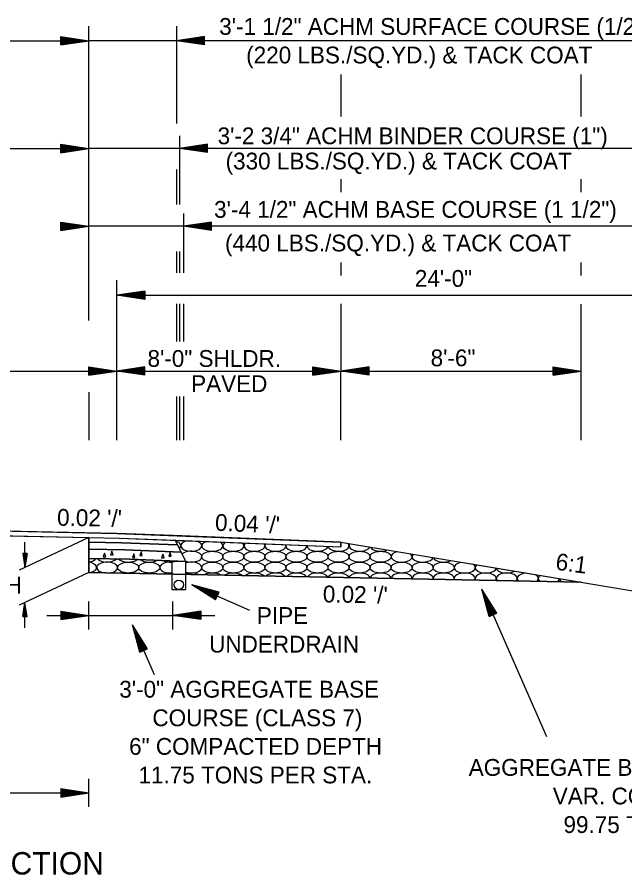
# Model space of a CAD drawing. Extents: x 1371763 to 1372860, y 385599 to 385872.
# Drawn here: x 1372369.02 to 1372390.7, y 385656.56 to 385687.17 of the extents above; entities that cross this region are included whole.
import ezdxf

# ---------------------------------------------------------------- set-up
doc = ezdxf.new("R2010")
doc.units = 0
doc.layers.add('R_Draft', color=7, linetype='Continuous')

msp = doc.modelspace()

# ---------------------------------------------------------------- linework, layer by layer
at = {"layer": 'R_Draft'}
for p, q in [((1372371.578, 385676.343), (1372371.579, 385686.852)), ((1372374.706, 385686.852), (1372374.706, 385683.373)), ((1372370.579, 385686.48), (1372371.579, 385686.33)), ((1372370.579, 385686.18), (1372370.579, 385686.48)), ((1372375.706, 385686.48), (1372374.706, 385686.33)), ((1372375.706, 385686.18), (1372375.706, 385686.48)), ((1372349.579, 385686.33), (1372371.579, 385686.33)), ((1372370.579, 385686.455), (1372371.412, 385686.33)), ((1372370.579, 385686.43), (1372371.24, 385686.33)), ((1372370.579, 385686.405), (1372371.074, 385686.33)), ((1372370.579, 385686.379), (1372370.904, 385686.33)), ((1372370.579, 385686.354), (1372370.737, 385686.33)), ((1372370.579, 385686.18), (1372371.579, 385686.33)), ((1372370.579, 385686.282), (1372370.904, 385686.33)), ((1372370.579, 385686.231), (1372371.24, 385686.33)), ((1372370.579, 385686.205), (1372371.412, 385686.33)), ((1372370.579, 385686.256), (1372371.074, 385686.33)), ((1372370.579, 385686.307), (1372370.737, 385686.33)), ((1372397.255, 385686.33), (1372371.579, 385686.33)), ((1372375.706, 385686.18), (1372374.706, 385686.33)), ((1372375.706, 385686.455), (1372374.873, 385686.33)), ((1372375.706, 385686.205), (1372374.873, 385686.33)), ((1372375.706, 385686.429), (1372375.045, 385686.33)), ((1372375.706, 385686.23), (1372375.045, 385686.33)), ((1372375.706, 385686.404), (1372375.211, 385686.33)), ((1372375.706, 385686.255), (1372375.211, 385686.33)), ((1372375.706, 385686.379), (1372375.381, 385686.33)), ((1372375.706, 385686.281), (1372375.381, 385686.33)), ((1372375.706, 385686.353), (1372375.548, 385686.33)), ((1372375.706, 385686.306), (1372375.548, 385686.33)), ((1372380.578, 385683.622), (1372380.578, 385685.122)), ((1372389.145, 385683.622), (1372389.145, 385685.122)), ((1372374.811, 385682.936), (1372374.811, 385680.483)), ((1372370.579, 385682.635), (1372371.579, 385682.485)), ((1372370.579, 385682.335), (1372370.579, 385682.635)), ((1372370.579, 385682.61), (1372371.412, 385682.485)), ((1372370.579, 385682.585), (1372371.24, 385682.485)), ((1372370.579, 385682.56), (1372371.074, 385682.485)), ((1372370.579, 385682.534), (1372370.904, 385682.485)), ((1372370.579, 385682.509), (1372370.737, 385682.485)), ((1372375.811, 385682.636), (1372374.811, 385682.486)), ((1372375.811, 385682.611), (1372374.978, 385682.486)), ((1372375.811, 385682.585), (1372375.15, 385682.486)), ((1372375.811, 385682.56), (1372375.316, 385682.486)), ((1372375.811, 385682.535), (1372375.486, 385682.486)), ((1372375.811, 385682.509), (1372375.653, 385682.486)), ((1372375.811, 385682.336), (1372375.811, 385682.636)), ((1372349.579, 385682.485), (1372371.579, 385682.485)), ((1372370.579, 385682.335), (1372371.579, 385682.485)), ((1372370.579, 385682.437), (1372370.904, 385682.485)), ((1372370.579, 385682.386), (1372371.24, 385682.485)), ((1372370.579, 385682.36), (1372371.412, 385682.485)), ((1372370.579, 385682.411), (1372371.074, 385682.485)), ((1372370.579, 385682.462), (1372370.737, 385682.485)), ((1372396.621, 385682.486), (1372371.579, 385682.486)), ((1372375.811, 385682.336), (1372374.811, 385682.486)), ((1372375.811, 385682.361), (1372374.978, 385682.486)), ((1372375.811, 385682.386), (1372375.15, 385682.486)), ((1372375.811, 385682.411), (1372375.316, 385682.486)), ((1372375.811, 385682.437), (1372375.486, 385682.486)), ((1372375.811, 385682.462), (1372375.653, 385682.486)), ((1372374.706, 385681.735), (1372374.706, 385680.483)), ((1372380.578, 385680.924), (1372380.578, 385681.39)), ((1372389.145, 385680.924), (1372389.145, 385681.39)), ((1372374.958, 385680.16), (1372374.958, 385678.045)), ((1372370.578, 385679.86), (1372371.578, 385679.71)), ((1372370.578, 385679.56), (1372370.578, 385679.86)), ((1372370.578, 385679.835), (1372371.411, 385679.71)), ((1372370.578, 385679.81), (1372371.239, 385679.71)), ((1372370.578, 385679.785), (1372371.073, 385679.71)), ((1372370.578, 385679.759), (1372370.903, 385679.71)), ((1372375.958, 385679.86), (1372374.958, 385679.71)), ((1372375.958, 385679.835), (1372375.125, 385679.71)), ((1372375.958, 385679.81), (1372375.297, 385679.71)), ((1372375.958, 385679.785), (1372375.464, 385679.71)), ((1372375.958, 385679.759), (1372375.633, 385679.71)), ((1372375.958, 385679.56), (1372375.958, 385679.86)), ((1372370.578, 385679.734), (1372370.736, 385679.71)), ((1372370.578, 385679.56), (1372371.578, 385679.71)), ((1372370.578, 385679.662), (1372370.903, 385679.71)), ((1372370.578, 385679.611), (1372371.239, 385679.71)), ((1372370.578, 385679.585), (1372371.411, 385679.71)), ((1372370.578, 385679.636), (1372371.073, 385679.71)), ((1372370.578, 385679.687), (1372370.736, 385679.71)), ((1372396.621, 385679.71), (1372371.579, 385679.71)), ((1372375.958, 385679.56), (1372374.958, 385679.71)), ((1372375.958, 385679.585), (1372375.125, 385679.71)), ((1372375.958, 385679.611), (1372375.297, 385679.71)), ((1372375.958, 385679.636), (1372375.464, 385679.71)), ((1372375.958, 385679.662), (1372375.633, 385679.71)), ((1372375.958, 385679.734), (1372375.8, 385679.71)), ((1372375.958, 385679.687), (1372375.8, 385679.71)), ((1372374.706, 385678.81), (1372374.706, 385678.045)), ((1372374.811, 385678.81), (1372374.811, 385678.045)), ((1372380.578, 385677.951), (1372380.578, 385678.416)), ((1372389.145, 385677.951), (1372389.145, 385678.416)), ((1372372.577, 385672.074), (1372372.578, 385677.788)), ((1372373.578, 385677.397), (1372372.578, 385677.247)), ((1372373.578, 385677.372), (1372372.745, 385677.247)), ((1372373.578, 385677.347), (1372372.917, 385677.247)), ((1372373.578, 385677.322), (1372373.084, 385677.247)), ((1372373.578, 385677.296), (1372373.253, 385677.247)), ((1372373.578, 385677.397), (1372373.578, 385677.097)), ((1372372.578, 385677.247), (1372396.577, 385677.247)), ((1372373.578, 385677.097), (1372372.578, 385677.247)), ((1372373.578, 385677.122), (1372372.745, 385677.247)), ((1372373.578, 385677.148), (1372372.917, 385677.247)), ((1372373.578, 385677.173), (1372373.084, 385677.247)), ((1372373.578, 385677.198), (1372373.253, 385677.247)), ((1372373.578, 385677.271), (1372373.42, 385677.247)), ((1372373.578, 385677.224), (1372373.42, 385677.247)), ((1372374.706, 385676.937), (1372374.706, 385675.595)), ((1372374.811, 385676.937), (1372374.811, 385675.595)), ((1372374.958, 385676.937), (1372374.958, 385675.595)), ((1372380.577, 385672.074), (1372380.578, 385676.935)), ((1372389.15, 385672.069), (1372389.15, 385676.934)), ((1372360.578, 385674.541), (1372372.578, 385674.541)), ((1372371.578, 385674.691), (1372372.578, 385674.541)), ((1372371.578, 385674.391), (1372371.578, 385674.691)), ((1372371.578, 385674.666), (1372372.411, 385674.541)), ((1372371.578, 385674.64), (1372372.239, 385674.541)), ((1372371.578, 385674.615), (1372372.072, 385674.541)), ((1372371.578, 385674.59), (1372371.903, 385674.541)), ((1372371.578, 385674.564), (1372371.736, 385674.541)), ((1372371.578, 385674.391), (1372372.578, 385674.541)), ((1372371.578, 385674.492), (1372371.903, 385674.541)), ((1372371.578, 385674.441), (1372372.239, 385674.541)), ((1372371.578, 385674.416), (1372372.411, 385674.541)), ((1372371.578, 385674.466), (1372372.072, 385674.541)), ((1372371.578, 385674.517), (1372371.736, 385674.541)), ((1372373.578, 385674.691), (1372372.578, 385674.541)), ((1372373.578, 385674.391), (1372372.578, 385674.541)), ((1372372.578, 385674.541), (1372380.578, 385674.541)), ((1372373.578, 385674.666), (1372372.745, 385674.541)), ((1372373.578, 385674.416), (1372372.745, 385674.541)), ((1372373.578, 385674.64), (1372372.917, 385674.541)), ((1372373.578, 385674.441), (1372372.917, 385674.541)), ((1372373.578, 385674.615), (1372373.083, 385674.541)), ((1372373.578, 385674.466), (1372373.083, 385674.541)), ((1372373.578, 385674.59), (1372373.253, 385674.541)), ((1372373.578, 385674.492), (1372373.253, 385674.541)), ((1372373.578, 385674.564), (1372373.42, 385674.541)), ((1372373.578, 385674.517), (1372373.42, 385674.541)), ((1372373.578, 385674.391), (1372373.578, 385674.691)), ((1372379.578, 385674.691), (1372380.578, 385674.541)), ((1372379.578, 385674.391), (1372379.578, 385674.691)), ((1372379.578, 385674.666), (1372380.411, 385674.541)), ((1372379.578, 385674.64), (1372380.239, 385674.541)), ((1372379.578, 385674.615), (1372380.072, 385674.541)), ((1372379.578, 385674.59), (1372379.903, 385674.541)), ((1372379.578, 385674.564), (1372379.736, 385674.541)), ((1372379.578, 385674.391), (1372380.578, 385674.541)), ((1372379.578, 385674.492), (1372379.903, 385674.541)), ((1372379.578, 385674.441), (1372380.239, 385674.541)), ((1372379.578, 385674.416), (1372380.411, 385674.541)), ((1372379.578, 385674.466), (1372380.072, 385674.541)), ((1372379.578, 385674.517), (1372379.736, 385674.541)), ((1372381.578, 385674.691), (1372380.578, 385674.541)), ((1372381.578, 385674.391), (1372380.578, 385674.541)), ((1372380.578, 385674.541), (1372389.149, 385674.54)), ((1372381.578, 385674.666), (1372380.745, 385674.541)), ((1372381.578, 385674.416), (1372380.745, 385674.541)), ((1372381.578, 385674.64), (1372380.917, 385674.541)), ((1372381.578, 385674.441), (1372380.917, 385674.541)), ((1372381.578, 385674.615), (1372381.083, 385674.541)), ((1372381.578, 385674.466), (1372381.083, 385674.541)), ((1372381.578, 385674.59), (1372381.253, 385674.541)), ((1372381.578, 385674.492), (1372381.253, 385674.541)), ((1372381.578, 385674.564), (1372381.42, 385674.541)), ((1372381.578, 385674.517), (1372381.42, 385674.541)), ((1372381.578, 385674.391), (1372381.578, 385674.691)), ((1372388.15, 385674.69), (1372389.15, 385674.54)), ((1372388.15, 385674.39), (1372388.15, 385674.69)), ((1372388.15, 385674.665), (1372388.983, 385674.54)), ((1372388.15, 385674.639), (1372388.811, 385674.54)), ((1372388.15, 385674.614), (1372388.644, 385674.54)), ((1372388.15, 385674.589), (1372388.475, 385674.54)), ((1372388.15, 385674.563), (1372388.308, 385674.54)), ((1372388.15, 385674.39), (1372389.15, 385674.54)), ((1372388.15, 385674.491), (1372388.475, 385674.54)), ((1372388.15, 385674.44), (1372388.811, 385674.54)), ((1372388.15, 385674.415), (1372388.983, 385674.54)), ((1372388.15, 385674.465), (1372388.644, 385674.54)), ((1372388.15, 385674.516), (1372388.308, 385674.54)), ((1372371.578, 385673.791), (1372371.578, 385672.074)), ((1372374.706, 385673.632), (1372374.706, 385672.074)), ((1372374.811, 385673.632), (1372374.811, 385672.074)), ((1372374.958, 385673.632), (1372374.958, 385672.074)), ((1372360.579, 385668.989), (1372372.577, 385668.749)), ((1372360.579, 385668.823), (1372372.661, 385668.581)), ((1372372.577, 385668.749), (1372380.577, 385668.43)), ((1372371.578, 385668.603), (1372369.091, 385667.431)), ((1372369.303, 385667.531), (1372369.303, 385668.431)), ((1372371.578, 385668.603), (1372371.578, 385668.436)), ((1372371.578, 385668.436), (1372371.578, 385668.186)), ((1372372.661, 385668.581), (1372380.577, 385668.265)), ((1372374.664, 385668.501), (1372374.748, 385668.333)), ((1372380.577, 385668.43), (1372396.577, 385665.763)), ((1372380.577, 385668.43), (1372380.577, 385668.265)), ((1372371.578, 385668.186), (1372371.578, 385667.853)), ((1372374.748, 385668.333), (1372374.854, 385668.121)), ((1372374.854, 385668.121), (1372375.022, 385667.784)), ((1372369.228, 385668.031), (1372369.303, 385667.531)), ((1372369.378, 385668.031), (1372369.228, 385668.031)), ((1372369.241, 385668.031), (1372369.303, 385667.615)), ((1372369.254, 385668.031), (1372369.303, 385667.701)), ((1372369.266, 385668.031), (1372369.303, 385667.784)), ((1372369.279, 385668.031), (1372369.303, 385667.869)), ((1372369.292, 385668.031), (1372369.303, 385667.952)), ((1372369.378, 385668.031), (1372369.303, 385667.531)), ((1372369.328, 385668.031), (1372369.303, 385667.869)), ((1372369.353, 385668.031), (1372369.303, 385667.701)), ((1372369.366, 385668.031), (1372369.303, 385667.615)), ((1372369.341, 385668.031), (1372369.303, 385667.784)), ((1372369.315, 385668.031), (1372369.303, 385667.952)), ((1372371.578, 385667.853), (1372371.578, 385667.353)), ((1372371.578, 385667.353), (1372369.091, 385666.181)), ((1372371.578, 385667.353), (1372389.145, 385667.001)), ((1372376.106, 385666.374), (1372375.251, 385666.914)), ((1372376.226, 385666.649), (1372375.251, 385666.914)), ((1372375.251, 385666.914), (1372377.318, 385666.005)), ((1372376.116, 385666.397), (1372375.404, 385666.847)), ((1372376.216, 385666.626), (1372375.404, 385666.847)), ((1372376.206, 385666.603), (1372375.561, 385666.778)), ((1372376.126, 385666.421), (1372375.561, 385666.778)), ((1372376.136, 385666.444), (1372375.713, 385666.711)), ((1372376.196, 385666.58), (1372375.713, 385666.711)), ((1372376.186, 385666.557), (1372375.869, 385666.643)), ((1372376.146, 385666.467), (1372375.869, 385666.643)), ((1372376.175, 385666.533), (1372376.021, 385666.575)), ((1372376.157, 385666.49), (1372376.021, 385666.575)), ((1372376.106, 385666.374), (1372376.226, 385666.649)), ((1372385.863, 385665.778), (1372385.598, 385666.754)), ((1372386.137, 385665.899), (1372385.598, 385666.754)), ((1372385.598, 385666.754), (1372387.905, 385661.501)), ((1372385.885, 385665.788), (1372385.665, 385666.601)), ((1372386.114, 385665.889), (1372385.665, 385666.601)), ((1372369.229, 385665.781), (1372369.304, 385666.281)), ((1372369.379, 385665.781), (1372369.304, 385666.281)), ((1372369.304, 385665.381), (1372369.304, 385666.281)), ((1372371.578, 385665.318), (1372371.578, 385666.318)), ((1372374.579, 385665.318), (1372374.579, 385666.318)), ((1372386.091, 385665.879), (1372385.734, 385666.444)), ((1372385.909, 385665.799), (1372385.734, 385666.444)), ((1372385.932, 385665.809), (1372385.801, 385666.292)), ((1372386.068, 385665.869), (1372385.801, 385666.292)), ((1372369.241, 385665.781), (1372369.304, 385666.198)), ((1372369.254, 385665.781), (1372369.304, 385666.112)), ((1372369.267, 385665.781), (1372369.304, 385666.028)), ((1372369.366, 385665.781), (1372369.304, 385666.198)), ((1372369.354, 385665.781), (1372369.304, 385666.112)), ((1372369.341, 385665.781), (1372369.304, 385666.028)), ((1372370.578, 385665.968), (1372371.578, 385665.818)), ((1372370.578, 385665.968), (1372370.578, 385665.668)), ((1372375.579, 385665.968), (1372374.579, 385665.818)), ((1372375.579, 385665.968), (1372375.579, 385665.668)), ((1372386.045, 385665.858), (1372385.869, 385666.136)), ((1372385.955, 385665.819), (1372385.869, 385666.136)), ((1372386.021, 385665.848), (1372385.936, 385665.983)), ((1372385.978, 385665.829), (1372385.936, 385665.983)), ((1372369.229, 385665.781), (1372369.379, 385665.781)), ((1372369.28, 385665.781), (1372369.304, 385665.944)), ((1372369.292, 385665.781), (1372369.304, 385665.86)), ((1372369.328, 385665.781), (1372369.304, 385665.944)), ((1372369.316, 385665.781), (1372369.304, 385665.86)), ((1372370.079, 385665.818), (1372376.079, 385665.818)), ((1372370.578, 385665.943), (1372371.411, 385665.818)), ((1372370.578, 385665.918), (1372371.239, 385665.818)), ((1372370.578, 385665.893), (1372371.072, 385665.818)), ((1372370.578, 385665.867), (1372370.903, 385665.818)), ((1372370.578, 385665.842), (1372370.736, 385665.818)), ((1372370.578, 385665.668), (1372371.578, 385665.818)), ((1372370.578, 385665.769), (1372370.903, 385665.818)), ((1372370.578, 385665.719), (1372371.239, 385665.818)), ((1372370.578, 385665.693), (1372371.411, 385665.818)), ((1372370.578, 385665.744), (1372371.072, 385665.818)), ((1372370.578, 385665.795), (1372370.736, 385665.818)), ((1372375.579, 385665.668), (1372374.579, 385665.818)), ((1372375.579, 385665.943), (1372374.746, 385665.818)), ((1372375.579, 385665.693), (1372374.746, 385665.818)), ((1372375.579, 385665.918), (1372374.918, 385665.818)), ((1372375.579, 385665.719), (1372374.918, 385665.818)), ((1372375.579, 385665.893), (1372375.085, 385665.818)), ((1372375.579, 385665.744), (1372375.085, 385665.818)), ((1372375.579, 385665.867), (1372375.254, 385665.818)), ((1372375.579, 385665.769), (1372375.254, 385665.818)), ((1372375.579, 385665.842), (1372375.421, 385665.818)), ((1372375.579, 385665.795), (1372375.421, 385665.818)), ((1372385.863, 385665.778), (1372386.137, 385665.899)), ((1372373.399, 385664.509), (1372373.134, 385665.485)), ((1372373.674, 385664.63), (1372373.134, 385665.485)), ((1372373.134, 385665.485), (1372373.913, 385663.712)), ((1372373.422, 385664.52), (1372373.202, 385665.332)), ((1372373.651, 385664.62), (1372373.202, 385665.332)), ((1372373.628, 385664.61), (1372373.271, 385665.175)), ((1372373.445, 385664.53), (1372373.271, 385665.175)), ((1372373.468, 385664.54), (1372373.338, 385665.023)), ((1372373.605, 385664.6), (1372373.338, 385665.023)), ((1372373.581, 385664.589), (1372373.406, 385664.867)), ((1372373.492, 385664.55), (1372373.406, 385664.867)), ((1372373.399, 385664.509), (1372373.674, 385664.63)), ((1372373.558, 385664.579), (1372373.473, 385664.714)), ((1372373.515, 385664.56), (1372373.473, 385664.714)), ((1372371.579, 385658.987), (1372371.579, 385659.987)), ((1372370.579, 385659.637), (1372371.579, 385659.487)), ((1372370.579, 385659.637), (1372370.579, 385659.337)), ((1372370.579, 385659.612), (1372371.412, 385659.487)), ((1372370.579, 385659.587), (1372371.24, 385659.487)), ((1372370.579, 385659.562), (1372371.074, 385659.487)), ((1372370.579, 385659.536), (1372370.904, 385659.487)), ((1372349.579, 385659.487), (1372371.579, 385659.487)), ((1372370.579, 385659.511), (1372370.737, 385659.487)), ((1372370.579, 385659.337), (1372371.579, 385659.487)), ((1372370.579, 385659.438), (1372370.904, 385659.487)), ((1372370.579, 385659.388), (1372371.24, 385659.487)), ((1372370.579, 385659.362), (1372371.412, 385659.487)), ((1372370.579, 385659.413), (1372371.074, 385659.487)), ((1372370.579, 385659.464), (1372370.737, 385659.487))]:
    msp.add_line(p, q, dxfattribs=at)
for points in [[(1372360.579, 385668.989), (1372348.577, 385668.749), (1372346.58, 385668.67), (1372340.576, 385668.429), (1372340.576, 385668.264), (1372346.478, 385668.5), (1372348.493, 385668.581), (1372349.58, 385668.603), (1372360.579, 385668.823), (1372371.578, 385668.603), (1372372.661, 385668.581), (1372374.682, 385668.5), (1372380.577, 385668.265), (1372380.577, 385668.43), (1372374.597, 385668.669), (1372372.577, 385668.749)], [(1372371.578, 385668.603), (1372372.661, 385668.581), (1372374.664, 385668.501), (1372374.748, 385668.333), (1372372.745, 385668.413), (1372371.578, 385668.436)], [(1372372.872, 385668.16), (1372371.578, 385668.186), (1372371.578, 385668.436), (1372372.745, 385668.413), (1372374.748, 385668.333), (1372374.874, 385668.08)], [(1372371.579, 385667.353), (1372371.579, 385667.853), (1372373.04, 385667.824), (1372375.042, 385667.743), (1372374.874, 385668.08), (1372374.748, 385668.333), (1372374.664, 385668.501), (1372380.577, 385668.265), (1372380.577, 385668.43), (1372389.145, 385667.001)], [(1372371.578, 385668.186), (1372372.872, 385668.16), (1372374.874, 385668.08), (1372375.042, 385667.743), (1372373.04, 385667.824), (1372371.579, 385667.853)], [(1372374.539, 385667.743), (1372374.539, 385666.746), (1372375.042, 385666.746), (1372375.042, 385667.743)]]:
    msp.add_lwpolyline(points, close=True, dxfattribs=at)
for points in [[(1372371.578, 385668.436), (1372372.745, 385668.413), (1372374.748, 385668.333)], [(1372371.578, 385668.186), (1372372.872, 385668.16), (1372374.874, 385668.08)], [(1372372.405, 385668.108), (1372372.357, 385667.975), (1372372.445, 385667.978), (1372372.405, 385668.108)], [(1372371.578, 385667.853), (1372373.04, 385667.824), (1372375.042, 385667.743)], [(1372372.146, 385668.042), (1372372.098, 385667.909), (1372372.186, 385667.912), (1372372.146, 385668.042)], [(1372373.186, 385668.021), (1372373.138, 385667.888), (1372373.226, 385667.892), (1372373.186, 385668.021)], [(1372373.445, 385668.087), (1372373.397, 385667.954), (1372373.485, 385667.958), (1372373.445, 385668.087)], [(1372374.226, 385668), (1372374.177, 385667.867), (1372374.265, 385667.871), (1372374.226, 385668)], [(1372374.485, 385668.066), (1372374.436, 385667.933), (1372374.524, 385667.937), (1372374.485, 385668.066)]]:
    msp.add_lwpolyline(points, dxfattribs=at)
msp.add_circle((1372374.791, 385666.913), 0.167, dxfattribs=at)
for centre, start_param, end_param in [((1372374.486, 385668.305), 5.755907, 7.317222), ((1372375.237, 385668.305), 1.964767, 7.305932), ((1372375.987, 385668.305), 2.23566, 7.035039), ((1372376.737, 385668.305), 2.44182, 6.828879), ((1372375.237, 385667.916), 1.191424, 2.634248), ((1372377.488, 385668.305), 2.620801, 6.649898), ((1372378.238, 385668.305), 2.785542, 6.485157), ((1372378.988, 385668.305), 2.942774, 6.327925), ((1372379.738, 385668.305), 3.097007, 6.173692), ((1372380.489, 385668.305), 3.252024, 6.725832), ((1372381.239, 385668.305), 2.758312, 6.043762), ((1372381.989, 385668.305), 3.401659, 5.400415), ((1372371.485, 385667.916), 4.965359, 5.923945), ((1372372.236, 385667.916), 3.506183, 5.841397), ((1372372.986, 385667.916), 3.591755, 5.724784), ((1372373.736, 385667.916), 3.729386, 5.541225), ((1372375.237, 385667.916), 4.155696, 7.47461), ((1372382.739, 385667.916), 1.98169, 6.820383), ((1372383.49, 385667.916), 2.692172, 6.109902), ((1372384.24, 385667.916), 3.325275, 5.476799), ((1372371.485, 385667.527), 5.150657, 7.601046), ((1372372.236, 385667.527), 4.936783, 10.693982), ((1372374.486, 385667.527), 1.430431, 4.852754), ((1372374.486, 385667.916), 3.944882, 5.325729), ((1372375.237, 385667.527), 4.167462, 8.332235), ((1372384.99, 385667.527), 1.875634, 6.449024), ((1372384.99, 385667.527), 0.165838, 0.643254), ((1372385.741, 385667.527), 2.625417, 6.176656), ((1372386.491, 385667.527), 3.251925, 5.550148), ((1372372.986, 385667.139), 1.233481, 1.830913), ((1372373.736, 385667.139), 1.03419, 2.030205), ((1372374.486, 385667.139), 1.432717, 2.173433), ((1372375.237, 385667.139), 0.771242, 2.115723), ((1372375.987, 385667.139), 0.665043, 2.399352), ((1372376.737, 385667.139), 0.567687, 2.496707), ((1372377.488, 385667.139), 0.476523, 2.587872), ((1372378.238, 385667.139), 0.389851, 2.674543), ((1372378.988, 385667.139), 0.306492, 2.757902), ((1372379.738, 385667.139), 0.225566, 2.838828), ((1372380.489, 385667.139), 0.146378, 2.918016), ((1372381.239, 385667.139), 0.06835, 2.996044), ((1372381.989, 385667.139), 6.274157, 9.356608), ((1372382.739, 385667.139), 6.196956, 9.43381), ((1372383.49, 385667.139), 0.860713, 3.228111), ((1372383.49, 385667.139), 6.119468, 7.143898), ((1372384.24, 385667.139), 0.565159, 3.306363), ((1372384.24, 385667.139), 6.041216, 6.848344), ((1372384.99, 385667.139), 0.327812, 3.385902), ((1372385.741, 385667.139), 0.114284, 3.467329), ((1372384.99, 385667.139), 5.961678, 6.610998), ((1372386.491, 385667.139), 0.775395, 3.551375), ((1372386.491, 385667.139), 5.796204, 7.05858), ((1372387.241, 385667.139), 1.750469, 3.638977), ((1372387.241, 385667.139), 0.511642, 0.768419), ((1372387.241, 385667.139), 5.708603, 6.794828), ((1372387.991, 385667.139), 2.557722, 3.731412), ((1372385.741, 385667.139), 5.88025, 6.39747), ((1372387.991, 385667.139), 5.616168, 6.244351), ((1372388.742, 385667.139), 3.180918, 3.830548), ((1372388.742, 385667.139), 5.517032, 5.621155)]:
    msp.add_ellipse(centre, major_axis=(0.375, 0), ratio=0.517889, start_param=start_param, end_param=end_param, dxfattribs=at)
for centre in [(1372375.987, 385667.916), (1372376.737, 385667.916), (1372377.488, 385667.916), (1372378.238, 385667.916), (1372378.988, 385667.916), (1372379.738, 385667.916), (1372380.489, 385667.916), (1372381.239, 385667.916), (1372381.989, 385667.916), (1372372.986, 385667.527), (1372373.736, 385667.527), (1372375.987, 385667.527), (1372376.737, 385667.527), (1372377.488, 385667.527), (1372378.238, 385667.527), (1372378.988, 385667.527), (1372379.738, 385667.527), (1372380.489, 385667.527), (1372381.239, 385667.527), (1372381.989, 385667.527), (1372382.739, 385667.527), (1372383.49, 385667.527), (1372384.24, 385667.527)]:
    msp.add_ellipse(centre, major_axis=(0.375, 0), ratio=0.517889, dxfattribs=at)

# ---------------------------------------------------------------- texts
for s, rotation, p in [('3\'-1 1/2" ACHM SURFACE COURSE (1/2")', 0, (1372376.233, 385686.54)), ('(220 LBS./SQ.YD.) & TACK COAT', 0, (1372377.195, 385685.52)), ('3\'-2 3/4" ACHM BINDER COURSE (1")', 0, (1372376.175, 385682.636)), ('(330 LBS./SQ.YD.) & TACK COAT', 0, (1372376.461, 385681.736)), ('3\'-4 1/2" ACHM BASE COURSE (1 1/2")', 360, (1372376.05, 385680.01)), ('(440 LBS./SQ.YD.) & TACK COAT', 360, (1372376.44, 385678.81)), ('8\'-0" SHLDR.', 360, (1372373.675, 385674.69)), ('8\'-6"', 360, (1372383.775, 385674.711)), ('PAVED', 360, (1372375.231, 385673.79)), ("0.02 '/'", 359.0147, (1372370.445, 385669.022)), ("0.04 '/'", 357.6223, (1372376.074, 385668.843)), ('6:1', 352.2846, (1372388.207, 385667.454)), ("0.02 '/'", 359.0147, (1372379.926, 385666.287)), ('PIPE', 360, (1372377.576, 385665.514)), ('UNDERDRAIN', 360, (1372375.873, 385664.494)), ('3\'-0" AGGREGATE BASE ', 360, (1372372.668, 385662.885)), ('COURSE (CLASS 7)', 360, (1372373.849, 385661.865)), ('6" COMPACTED DEPTH', 360, (1372373.018, 385660.845)), ('AGGREGATE BASE COURSE (CLASS 7)', 360, (1372385.133, 385660.094)), ('11.75 TONS PER STA.', 360, (1372373.353, 385659.825)), ('VAR. COMPACTED DEPTH', 360, (1372388.133, 385659.074)), ('99.75 TONS PER STA.', 360, (1372388.515, 385658.054))]:
    msp.add_text(s, height=0.6, rotation=rotation, dxfattribs=at).set_placement(p)
for s, height, p in [('24\'-0"', 0.6, (1372383.211, 385677.547)), ('15" NOTCH', 0.6, (1372364.937, 385666.6)), ('HWY. 72 - TWO LANE NOTCH AND WIDEN SECTION', 0.8, (1372345.729, 385656.572))]:
    msp.add_text(s, height=height, dxfattribs=at).set_placement(p)

doc.saveas('drawing.dxf')
